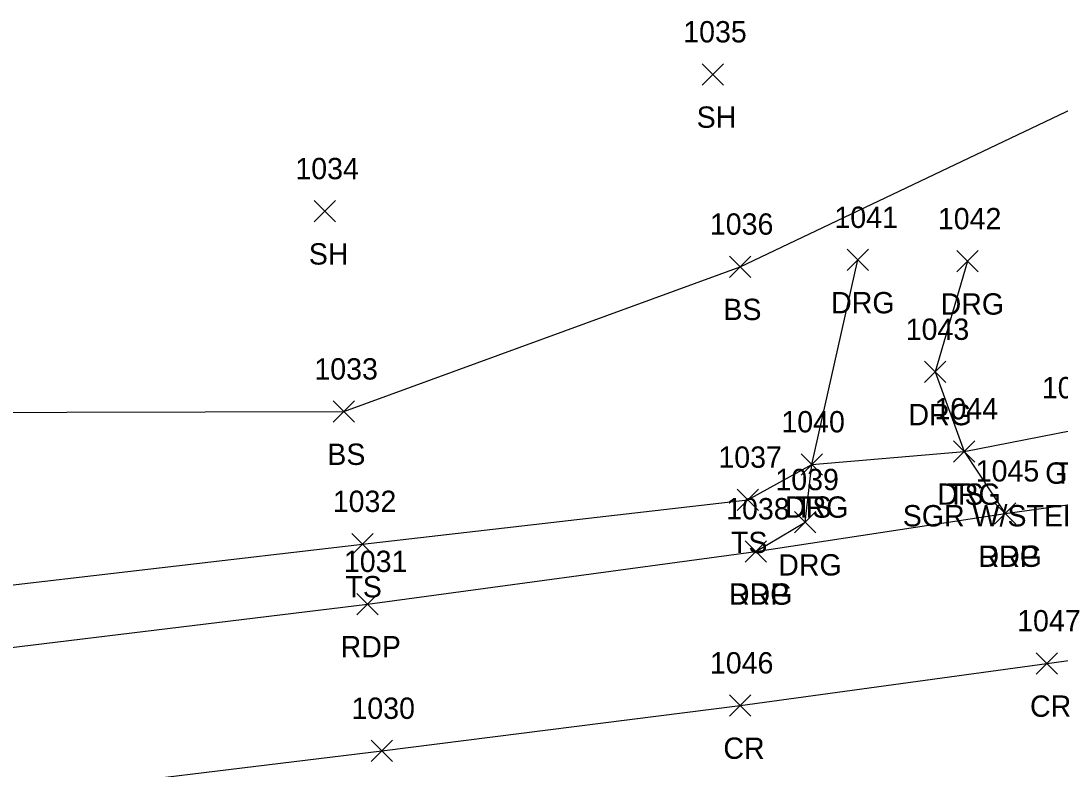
# Model space of a CAD drawing. Extents: x 1600395 to 1603269, y 874955 to 877143.
# Drawn here: x 1601626.7 to 1601724, y 875220.3 to 875290.4 of the extents above; entities that cross this region are included whole.
import ezdxf

# ---------------------------------------------------------------- set-up
doc = ezdxf.new("R2010")
doc.units = 0
for name, color, linetype in [('L_A', 7, 'Continuous'), ('L_I', 7, 'Continuous'), ('L_TIC', 7, 'Continuous'), ('LELB', 7, 'Continuous'), ('P_A', 7, 'Continuous'), ('P_I', 7, 'Continuous'), ('P_TIC', 7, 'Continuous'), ('PET', 7, 'Continuous'), ('PRC', 7, 'Continuous'), ('R_A', 7, 'Continuous'), ('R_C', 7, 'Continuous'), ('R_I', 7, 'Continuous'), ('R_TIC', 7, 'Continuous'), ('RDG', 7, 'Continuous')]:
    doc.layers.add(name, color=color, linetype=linetype)

msp = doc.modelspace()

# ---------------------------------------------------------------- linework, layer by layer
at = {"layer": 'L_TIC'}
for points in [[(1601690.491, 875284.362), (1601692.491, 875286.362)], [(1601692.491, 875284.362), (1601690.491, 875286.362)], [(1601654.16, 875271.543), (1601656.16, 875273.543)], [(1601656.16, 875271.543), (1601654.16, 875273.543)], [(1601693.042, 875266.342), (1601695.042, 875268.342)], [(1601695.042, 875266.342), (1601693.042, 875268.342)], [(1601655.941, 875252.767), (1601657.941, 875254.767)], [(1601657.941, 875252.767), (1601655.941, 875254.767)], [(1601714.033, 875249.029), (1601716.033, 875251.029)], [(1601716.033, 875249.029), (1601714.033, 875251.029)], [(1601699.77, 875247.817), (1601701.77, 875249.817)], [(1601701.77, 875247.817), (1601699.77, 875249.817)], [(1601693.784, 875244.501), (1601695.784, 875246.501)], [(1601695.784, 875244.501), (1601693.784, 875246.501)], [(1601657.665, 875240.356), (1601659.665, 875242.356)], [(1601659.665, 875240.356), (1601657.665, 875242.356)]]:
    msp.add_lwpolyline(points, dxfattribs=at)
at = {"layer": 'LELB'}
for points in [[(1601507.847, 875247.89), (1601547.421, 875248.527), (1601578.347, 875245.47), (1601617.951, 875253.676), (1601656.941, 875253.767), (1601694.042, 875267.342), (1601727.194, 875283.102)], [(1601507.321, 875231.194), (1601546.9, 875233.686), (1601579.202, 875234.27), (1601621.109, 875236.954), (1601658.665, 875241.356), (1601694.784, 875245.501), (1601700.77, 875248.817), (1601715.033, 875250.029), (1601725.08, 875252.006), (1601746.273, 875257.428)]]:
    msp.add_lwpolyline(points, dxfattribs=at)
at = {"layer": 'P_TIC'}
for points in [[(1601717.889, 875243.213), (1601719.889, 875245.213)], [(1601719.889, 875243.213), (1601717.889, 875245.213)], [(1601694.513, 875239.663), (1601696.513, 875241.663)], [(1601696.513, 875239.663), (1601694.513, 875241.663)], [(1601658.141, 875234.732), (1601660.141, 875236.732)], [(1601660.141, 875234.732), (1601658.141, 875236.732)], [(1601721.769, 875229.164), (1601723.769, 875231.164)], [(1601723.769, 875229.164), (1601721.769, 875231.164)], [(1601693.047, 875225.221), (1601695.047, 875227.221)], [(1601695.047, 875225.221), (1601693.047, 875227.221)], [(1601659.498, 875220.967), (1601661.498, 875222.967)], [(1601661.498, 875220.967), (1601659.498, 875222.967)]]:
    msp.add_lwpolyline(points, dxfattribs=at)
at = {"layer": 'PET'}
msp.add_lwpolyline([(1601414.027, 875231.868), (1601447.658, 875227.337), (1601480.387, 875224.741), (1601507.332, 875223.944), (1601546.886, 875225.235), (1601579.482, 875227.318), (1601621.881, 875231.182), (1601659.141, 875235.732), (1601695.513, 875240.663), (1601718.889, 875244.213), (1601760.24, 875249.955), (1601754.149, 875234.472), (1601747.535, 875218.619)], dxfattribs=at)
at = {"layer": 'PRC'}
msp.add_lwpolyline([(1601506.675, 875209.64), (1601547.643, 875210.928), (1601581.16, 875213.374), (1601623.527, 875217.485), (1601660.498, 875221.967), (1601694.047, 875226.221), (1601722.769, 875230.164), (1601754.149, 875234.472)], dxfattribs=at)
at = {"layer": 'R_TIC'}
for points in [[(1601704.086, 875266.974), (1601706.086, 875268.974)], [(1601706.086, 875266.974), (1601704.086, 875268.974)], [(1601714.342, 875266.851), (1601716.342, 875268.851)], [(1601716.342, 875266.851), (1601714.342, 875268.851)], [(1601711.331, 875256.486), (1601713.331, 875258.486)], [(1601713.331, 875256.486), (1601711.331, 875258.486)], [(1601714.033, 875249.029), (1601716.033, 875251.029)], [(1601716.033, 875249.029), (1601714.033, 875251.029)], [(1601699.77, 875247.817), (1601701.77, 875249.817)], [(1601701.77, 875247.817), (1601699.77, 875249.817)], [(1601717.889, 875243.213), (1601719.889, 875245.213)], [(1601719.889, 875243.213), (1601717.889, 875245.213)], [(1601699.132, 875242.402), (1601701.132, 875244.402)], [(1601701.132, 875242.402), (1601699.132, 875244.402)], [(1601694.513, 875239.663), (1601696.513, 875241.663)], [(1601696.513, 875239.663), (1601694.513, 875241.663)]]:
    msp.add_lwpolyline(points, dxfattribs=at)
at = {"layer": 'RDG'}
for points in [[(1601695.513, 875240.663), (1601700.132, 875243.402), (1601700.77, 875248.817), (1601705.086, 875267.974)], [(1601715.342, 875267.851), (1601712.331, 875257.486), (1601715.033, 875250.029), (1601718.889, 875244.213)]]:
    msp.add_lwpolyline(points, dxfattribs=at)

# ---------------------------------------------------------------- texts
at = {"layer": 'L_A'}
for s, p in [('SH', (1601689.979, 875280.362)), ('SH', (1601653.648, 875267.543)), ('BS', (1601692.483, 875262.342)), ('BS', (1601655.382, 875248.767)), ('TS', (1601723.489, 875247.006)), ('TS', (1601713.443, 875245.029)), ('TS', (1601699.18, 875243.817)), ('TS', (1601693.193, 875240.501)), ('TS', (1601657.074, 875236.356))]:
    msp.add_text(s, height=2, dxfattribs=at).set_placement(p)
at = {"layer": 'L_I'}
for s, p in [('1035', (1601688.719, 875288.362)), ('1034', (1601652.388, 875275.543)), ('1036', (1601691.215, 875270.342)), ('1033', (1601654.169, 875256.767)), ('1048', (1601722.308, 875255.006)), ('1044', (1601712.262, 875253.029)), ('1040', (1601697.912, 875251.817)), ('1037', (1601692.012, 875248.501)), ('1032', (1601655.893, 875244.356))]:
    msp.add_text(s, height=2, dxfattribs=at).set_placement(p)
at = {"layer": 'P_A'}
for s, p in [('RDP', (1601716.377, 875239.213)), ('RDP', (1601693.001, 875235.663)), ('RDP', (1601656.629, 875230.732)), ('CR', (1601721.202, 875225.164)), ('CR', (1601692.48, 875221.221))]:
    msp.add_text(s, height=2, dxfattribs=at).set_placement(p)
at = {"layer": 'P_I'}
for s, p in [('1045', (1601716.117, 875247.213)), ('1038', (1601692.741, 875243.663)), ('1031', (1601656.936, 875238.732)), ('1047', (1601719.998, 875233.164)), ('1046', (1601691.22, 875229.221)), ('1030', (1601657.64, 875224.967))]:
    msp.add_text(s, height=2, dxfattribs=at).set_placement(p)
at = {"layer": 'R_A'}
for s, p in [('DRG', (1601702.574, 875262.974)), ('DRG', (1601712.831, 875262.851)), ('DRG', (1601709.819, 875252.486)), ('GRL', (1601722.623, 875247.006)), ('DRG', (1601712.521, 875245.029)), ('DRG', (1601698.258, 875243.817)), ('DRG', (1601716.377, 875239.213)), ('DRG', (1601697.62, 875238.402)), ('DRG', (1601693.001, 875235.663))]:
    msp.add_text(s, height=2, dxfattribs=at).set_placement(p)
at = {"layer": 'R_C'}
msp.add_text('SGR W/STEEL POSTS', height=2, dxfattribs=at).set_placement((1601709.285, 875243.006))
at = {"layer": 'R_I'}
for s, p in [('1041', (1601702.881, 875270.974)), ('1042', (1601712.571, 875270.851)), ('1043', (1601709.56, 875260.486)), ('1048', (1601722.308, 875255.006)), ('1044', (1601712.262, 875253.029)), ('1040', (1601697.912, 875251.817)), ('1045', (1601716.117, 875247.213)), ('1039', (1601697.353, 875246.402)), ('1038', (1601692.741, 875243.663))]:
    msp.add_text(s, height=2, dxfattribs=at).set_placement(p)

doc.saveas('drawing.dxf')
